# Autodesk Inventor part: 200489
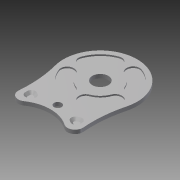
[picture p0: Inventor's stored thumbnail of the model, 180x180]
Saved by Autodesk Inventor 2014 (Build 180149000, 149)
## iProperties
Created: 2007-11
Part Number: 200489
Document SubType Name: Modeling
Designer: TH
Density: 7.85 g/cm^3
Mass: 170.344 g
Surface Area: 144.32 cm^2
Volume: 21.6998 cm^3
Material: Steel
Description: SIDE PIVOT PLATE
Appearance: Steel
Component Category: Lower Component
Author: TH
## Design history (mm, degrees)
sketch "Sketch1"
  geometry: L1 (0, 64.951)-(0, -116.705) reference; A1 r 39 centre (0, 0) between (37.727, -9.884) and (-37.727, -9.884); A2 r 8 centre (-26.125, -52.85) between (-34.096, -52.171) and (-21.585, -59.437); A3 r 8 centre (26.125, -52.85) between (21.585, -59.437) and (34.096, -52.171); A4 r 125 centre (-158.645, -41.565) between (-34.096, -52.171) and (-37.727, -9.884); A5 r 38.035 centre (0, -90.754) between (21.585, -59.437) and (-21.585, -59.437); A6 r 125 centre (158.645, -41.565) between (37.727, -9.884) and (34.096, -52.171); 1 further point
  constraints: 13 point on circle, 6 centre point, 4 tangent, 3 symmetric about line, 1 coincident, 1 point on line, 1 other
  dimensions: "d0" = 16 diameter of A2; "d2" = 78 diameter of A1; "d3" = 52.85 vertical distance of A2.centre point (0, 0); "d5" = 26.125 horizontal distance of A2.centre point (0, 0); "d8" = 317.29074 distance of A6.centre A4.centre; "d9" = 26.125 distance from line of L1 A3.centre; "d10" = 38.03504 radius of A5
extrude "Extrusion1" new body sketch "Sketch1" distance "d11" = 4; taper "d12" = 0 deg
sketch "Sketch2"
  geometry: L1 (-27.275, -50.476)-(-27.275, -48.224); L2 (-21.575, -51.515)-(-23.525, -52.641); L3 (-23.525, -46.059)-(-21.575, -47.185); L4 (0, -116.705)-(0, 64.951) reference; A1 r 39 centre (0, 0) between (37.727, -9.884) and (-37.727, -9.884) reference; A2 r 8 centre (-26.125, -52.85) between (-34.096, -52.171) and (-21.585, -59.437) reference; A3 r 38.035 centre (0, -90.754) between (21.585, -59.437) and (-21.585, -59.437) reference; A4 r 2.5 centre (-24.775, -48.224) between (-23.525, -46.059) and (-27.275, -48.224); A5 r 2.5 centre (-24.775, -50.476) between (-27.275, -50.476) and (-23.525, -52.641); A6 r 2.5 centre (-22.825, -49.35) between (-21.575, -51.515) and (-21.575, -47.185); 3 further points
  constraints: 9 point on circle, 6 end point, 6 tangent, 3 centre point, 3 point on line, 2 equal radius
  dimensions: "d13" = 60 deg angle of L2 L1; "d14" = 60 deg angle of L2 L3; "d15" = 2.5 radius of A4; "d16" = 22.825 horizontal distance of A1.centre A6.centre; "d17" = 49.35 vertical distance of A1.centre A6.centre; "d18" = 60 deg angle of L4 L2; "d19" = 1.95 horizontal distance of A4.centre A6.centre
extrude "Extrusion2" join sketch "Sketch2" distance "d20" = 2.5; taper "d21" = 0 deg
chamfer "Chamfer1" distance "d22" = 2.5; stored, may be unused: second distance "d23" = 2, angle "d24" = 45 deg
mirror "Mirror1"
sketch "Sketch3"
  geometry: L1 (-23.525, -46.059)-(-21.575, -47.185) reference; L2 (-21.575, -51.515)-(-23.525, -52.641) reference; L3 (-27.275, -50.476)-(-27.275, -48.224) reference; L4 (-22.65, -54.156)-(-20.7, -53.031); L5 (-20.7, -45.669)-(-22.65, -44.544); L6 (-29.025, -48.224)-(-29.025, -50.476); A1 r 2.5 centre (-22.825, -49.35) between (-21.575, -51.515) and (-21.575, -47.185) reference; A2 r 2.5 centre (-24.775, -50.476) between (-27.275, -50.476) and (-23.525, -52.641) reference; A3 r 2.5 centre (-24.775, -48.224) between (-23.525, -46.059) and (-27.275, -48.224) reference; A4 r 4.25 centre (-22.825, -49.35) between (-20.7, -53.031) and (-20.7, -45.669); A5 r 4.25 centre (-24.775, -48.224) between (-22.65, -44.544) and (-29.025, -48.224); A6 r 4.25 centre (-24.775, -50.476) between (-29.025, -50.476) and (-22.65, -54.156)
  constraints: 6 end point, 6 point on circle, 3 centre point, 5 other
  dimensions: "d30" = 1.75 distance between parallel lines of L4 L2
extrude "Extrusion3" cut sketch "Sketch3" distance "d25" = 2.5; taper "d26" = 0 deg
chamfer "Chamfer2" distance "d27" = 2.5; stored, may be unused: second distance "d28" = 2, angle "d29" = 45 deg
mirror "Mirror2"
sketch "Sketch4"
  geometry: L1 (0, 0)-(0, -45); C1 r 8.5 at (0, 0); C2 r 4 at (0, -45); 1 further point
  constraints: 2 centre point, 2 coincident, 2 end point, 1 vertical
  dimensions: "d31" = 17 diameter of C1; "d32" = 45 distance of L1.start L1.end; "d33" = 8 diameter of C2
extrude "Extrusion4" cut sketch "Sketch4" stored distance "d34" = 2.5; taper "d35" = 0 deg
sketch "Sketch5"
  geometry: L1 (-29.025, -50.476)-(-29.025, -48.224) reference; L2 (-2.8, 33.885)-(-2.8, 19.803); L3 (-19.843, 2.5)-(-33.908, 2.5); C1 r 8.5 at (0, 0) reference; A1 r 39 centre (0, 0) between (37.727, -9.884) and (-37.727, -9.884) reference; A2 r 34 centre (0, 0) between (-2.8, 33.885) and (-33.908, 2.5); A3 r 20 centre (0, 0) between (-2.8, 19.803) and (-19.843, 2.5)
  constraints: 4 end point, 4 point on circle, 2 centre point, 2 coincident, 1 parallel, 1 perpendicular
  dimensions: "d36" = 68 diameter of A2; "d37" = 40 diameter of A3; "d38" = 2.5 distance from line of L3 C1.centre; "d39" = 2.8 distance from line of C1.centre L2
extrude "Extrusion5" cut sketch "Sketch5" distance "d40" = 1.5; taper "d41" = 0 deg
fillet "Fillet1" dims "d42" = 6.75
pattern_circular "Circular Pattern1" dims angle "d44" = 360 deg
body "Solid1"
node "Projected Loop1"
